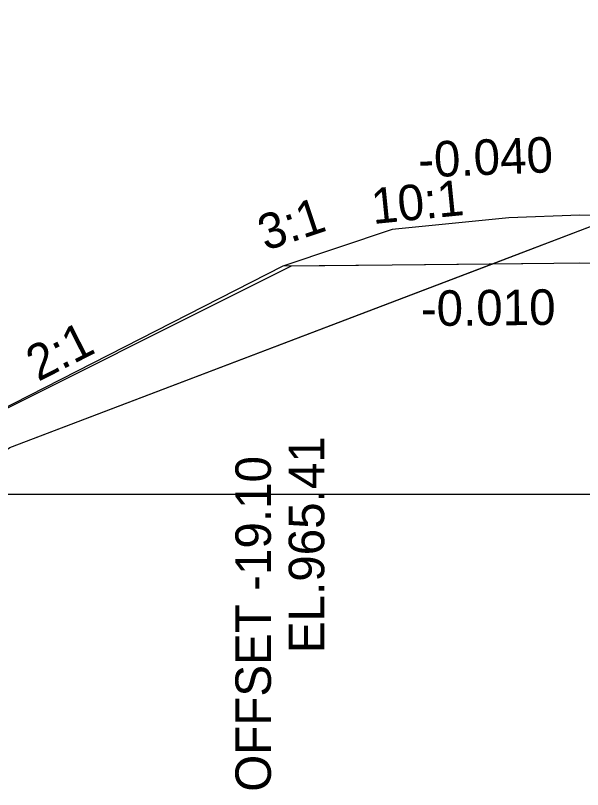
# Model space of a CAD drawing. Extents: x -192 to 2669, y -25 to 8040.
# Drawn here: x 2423.38 to 2439.33, y 4991.7 to 5013.45 of the extents above; entities that cross this region are included whole.
import ezdxf

# ---------------------------------------------------------------- set-up
doc = ezdxf.new("R2010")
doc.units = 0
for name, color, linetype in [('DESIGN - EARTHWORK - Shapes', 7, 'Continuous'), ('DESIGN - SHEET - Light Grid', 7, 'Continuous'), ('DESIGN - TYPICAL - Finished Grade and Subgrade', 7, 'Continuous'), ('DESIGN - TYPICAL - Finished Grade Slopes Text', 7, 'Continuous'), ('DESIGN - TYPICAL - Subgrade Cross Slope Text', 7, 'Continuous'), ('DESIGN - TYPICAL - Subgrade Tie Text', 7, 'Continuous'), ('SURVEY - GROUND - Top of Ground', 7, 'Continuous')]:
    doc.layers.add(name, color=color, linetype=linetype)

msp = doc.modelspace()

# ---------------------------------------------------------------- linework, layer by layer
at = {"layer": 'DESIGN - EARTHWORK - Shapes'}
for points in [[(2438.521, 5006.484), (2436.777, 5006.467), (2439.918, 5007.662), (2441.938, 5007.66), (2449.617, 5007.731), (2450, 5007.72), (2451.808, 5007.668), (2460.51, 5007.343), (2461.021, 5007.322), (2465.578, 5005.804), (2461.021, 5005.974), (2460.51, 5005.993), (2450, 5006.385), (2439.26, 5006.492)], [(2436.777, 5006.467), (2433.98, 5006.439), (2431.138, 5006.41), (2421.37, 5001.526), (2422.082, 5000.884), (2422.526, 5000.852), (2423.226, 5001.312)]]:
    msp.add_lwpolyline(points, close=True, dxfattribs=at)
at = {"layer": 'DESIGN - SHEET - Light Grid'}
msp.add_line((2300, 5000), (2450, 5000), dxfattribs=at)
at = {"layer": 'DESIGN - TYPICAL - Finished Grade and Subgrade'}
for p, q in [((2437.26, 5007.762), (2433.98, 5007.434)), ((2439.26, 5007.842), (2437.26, 5007.762)), ((2450, 5007.735), (2439.26, 5007.842)), ((2433.98, 5007.434), (2430.903, 5006.408)), ((2430.903, 5006.408), (2419.487, 5000.585)), ((2433.98, 5006.439), (2430.903, 5006.408)), ((2438.521, 5006.484), (2433.98, 5006.439)), ((2439.26, 5006.492), (2438.521, 5006.484)), ((2450, 5006.385), (2439.26, 5006.492))]:
    msp.add_line(p, q, dxfattribs=at)
at = {"layer": 'SURVEY - GROUND - Top of Ground'}
msp.add_lwpolyline([(2419.037, 5003.672), (2419.484, 5003.249), (2422.082, 5000.884), (2422.526, 5000.852), (2423.226, 5001.312), (2439.918, 5007.662), (2441.938, 5007.66), (2449.617, 5007.731), (2450, 5007.72), (2454.394, 5007.594), (2459.74, 5007.463), (2472.117, 5007.482), (2491.663, 5007.299), (2515.601, 5009.082), (2525.264, 5009.766), (2536.393, 5010.561), (2562.593, 5012.195), (2577.425, 5012.588), (2585.384, 5013.333), (2597.778, 5013.436), (2600, 5013.454)], dxfattribs=at)

# ---------------------------------------------------------------- texts
at = {"layer": 'DESIGN - TYPICAL - Finished Grade Slopes Text'}
for s, rotation, p in [('-0.040', 2.2906, (2434.728, 5008.897)), ('10:1', 5.7106, (2433.441, 5007.59)), ('3:1', 18.4349, (2430.412, 5006.83)), ('2:1', 26.8312, (2424.019, 5003.152))]:
    msp.add_text(s, height=1, rotation=rotation, dxfattribs=at).set_placement(p)
at = {"layer": 'DESIGN - TYPICAL - Subgrade Cross Slope Text'}
msp.add_text('-0.010', height=1, rotation=0.5729, dxfattribs=at).set_placement((2434.787, 5004.722))
at = {"layer": 'DESIGN - TYPICAL - Subgrade Tie Text'}
for s, p in [('EL.965.41', (2432.068, 4995.529)), ('OFFSET -19.10', (2430.568, 4991.633))]:
    msp.add_text(s, height=1, rotation=90, dxfattribs=at).set_placement(p)

doc.saveas('drawing.dxf')
